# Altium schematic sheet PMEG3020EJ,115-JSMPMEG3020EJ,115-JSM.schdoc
size 127 x 101 mm
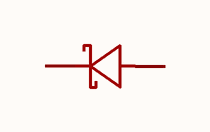
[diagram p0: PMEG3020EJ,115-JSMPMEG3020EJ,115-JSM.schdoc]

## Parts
D?  pmeg3020ej,115-jsm  [SOD-323_L1.7-W1.3-LS2.7-RD-1]  (value not drawn)

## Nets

Not connected (* = marked no-connect by the designer): D? 1(K) 2(A)

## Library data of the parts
D? = pmeg3020ej,115-jsm: 二极管配置:1个独立式;正向压降(Vf):420mV@1A；500mV@2A;直流反向耐压(Vr):40V;整流电流:2A;; Manufacturer: JSMSEMI(杰盛微); AddInBom: yes; ModelId: 6cb9e215dfa74358aef5a433493d9154; ModelTransform: 104.3305,51.181,0,0,0,0,0,0,0; Diode Configuration: 1个独立式; Voltage - DC Reverse(Vr): 40V; Current - Rectified: 2A; Reverse Leakage Current (Ir): 80uA@40V; Operating Junction Temperature Range: -50℃~+125℃; Non-Repetitive Peak Forward Surge Current: 20A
